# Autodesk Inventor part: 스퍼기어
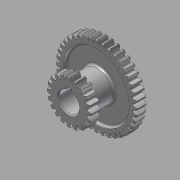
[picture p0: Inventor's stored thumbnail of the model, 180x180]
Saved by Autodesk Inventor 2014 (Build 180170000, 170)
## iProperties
Created: 2015-09
Part Number: 스퍼기어
Material: 강철, 연강
Document SubType Name: Modeling
Designer: mduedu
Density: 7.86 g/cm^3
Mass: 345.723 g
Surface Area: 225.641 cm^2
Volume: 43.9851 cm^3
Appearance: Steel
Author: mduedu
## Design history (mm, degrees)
sketch "스케치1"
  geometry: C1 r 38 at (0, 0); C2 r 40 at (0, 0); C3 r 35.5 at (0, 0); 1 further point
  constraints: 3 centre point, 3 coincident
  dimensions: "d0" = 76 diameter of C1; "d2" = 2 radial gap between concentric circles of C2 C1; "d3" = 71 diameter of C3 (computed from d0)
extrude "돌출1" new body sketch "스케치1" stored distance "d4" = 10; taper "d5" = 0 deg
sketch "스케치2"
  geometry: L1 (0, 35.5)-(0, -35.5); L2 (0, 0)-(40, 0); L3 (0, 0.57)-(39.996, 0.57); L4 (0, 1.57)-(39.969, 1.57); L5 (0, 2.07)-(39.946, 2.07); A1 r 35.5 centre (0, 0) between (0, 35.5) and (0, -35.5) reference; A2 r 40 centre (0, 0) between (40, 0) and (39.946, 2.07) reference; A3 r 9.234 centre (34.93, -7.149) between (39.996, 0.57) and (35.44, 2.07); A4 r 9.234 centre (34.93, 7.149) between (35.44, -2.07) and (39.996, -0.57); A5 r 40 centre (0, 0) between (39.996, -0.57) and (39.996, 0.57); A6 r 35.5 centre (0, 0) between (35.44, -2.07) and (35.44, 2.07); 4 further points
  constraints: 16 point on circle, 10 end point, 6 point on line, 4 centre point, 3 coincident, 3 parallel, 3 symmetric about line, 2 midpoint, 1 perpendicular, 1 vertical, 3 other
  dimensions: "d6" = 0.5 distance between parallel lines of L4 L5; "d8" = 1 distance between parallel lines of L3 L4; "d9" = 1.57 distance between parallel lines of L2 L4
extrude "돌출2" join sketch "스케치2" distance "d10" = 5; taper "d12" = 0 deg; dims "d11" = 5, "d13" = 0
fillet "모깎기1" dims "d17" = 0.5
chamfer "모따기1" distance "d21" = 1; stored, may be unused: second distance "d22" = 2, angle "d23" = 45 deg
sketch "스케치3"
  geometry: C1 r 32.5 at (0, 0); C2 r 15 at (0, 0); 1 further point
  constraints: 2 centre point, 2 coincident
  dimensions: "d27" = 65 diameter of C1; "d28" = 30 diameter of C2
extrude "돌출3" cut sketch "스케치3" distance "d29" = 3; taper "d30" = 0 deg
fillet "모깎기2" dims "d31" = 2
node "작업 평면2"
  node "작업 평면1"
sketch "스케치4"
  geometry: C1 r 15 at (0, 0) reference; 1 further point
extrude "돌출4" join sketch "스케치4" stored distance "d34" = 3; taper "d35" = 0 deg
sketch "스케치5"
  geometry: C1 r 17.5 at (0, 0); C2 r 20 at (0, 0); C3 r 22 at (0, 0); 1 further point
  constraints: 3 centre point, 3 coincident
  dimensions: "d36" = 40 diameter of C2; "d38" = 2 radial gap between concentric circles of C2 C3; "d39" = 35 diameter of C1 (= d36 - 2.5 x d38)
extrude "돌출6" join sketch "스케치5" distance "d46" = 10; taper "d47" = 0 deg
sketch "스케치6"
  geometry: L1 (0, 0)-(0, 22); L2 (-17.5, 0)-(17.5, 0); L3 (-0.57, 0)-(-0.57, 21.993); L4 (-1.57, 0)-(-1.57, 21.944); L5 (-2.07, 0)-(-2.07, 21.902); A1 r 22 centre (0, 0) between (0, 22) and (-0.57, 21.993) reference; A2 r 17.5 centre (0, 0) between (-17.5, 0) and (17.5, 0) reference; A3 r 9.431 centre (7.348, 16.868) between (-0.57, 21.993) and (-2.07, 17.377); A4 r 9.431 centre (-7.348, 16.868) between (2.07, 17.377) and (0.57, 21.993); A5 r 17.5 centre (0, 0) between (2.07, 17.377) and (-2.07, 17.377); A6 r 22 centre (0, 0) between (0.57, 21.993) and (-0.57, 21.993); 4 further points
  constraints: 16 point on circle, 10 end point, 5 point on line, 4 centre point, 3 coincident, 3 symmetric about line, 2 parallel, 2 perpendicular, 1 midpoint, 1 vertical, 3 other
  dimensions: "d40" = 0.5 distance between parallel lines of L4 L5; "d42" = 1 distance between parallel lines of L3 L4; "d43" = 1.57 distance between parallel lines of L1 L4
extrude "돌출5" join sketch "스케치6" distance "d44" = 10; taper "d45" = 0 deg
fillet "모깎기3" dims "d48" = 0.5
chamfer "모따기2" distance "d49" = 1; stored, may be unused: second distance "d50" = 2, angle "d51" = 45 deg
sketch "스케치7"
  geometry: C1 r 10 at (0, 0); 1 further point
  constraints: 1 centre point, 1 coincident
  dimensions: "d55" = 20 diameter of C1
extrude "돌출7" cut sketch "스케치7" stored distance "d56" = 10; taper "d57" = 0 deg
sketch "스케치8"
  geometry: L1 (-9.539, -3)-(-12.8, -3); L2 (-12.8, -3)-(-12.8, 3); L3 (-12.8, 3)-(-9.539, 3); L4 (-9.539, 3)-(-9.539, -3); A1 r 10 centre (0, 0) between (-9.539, -3) and (-9.539, 3) reference; 2 further points
  constraints: 8 end point, 3 point on circle, 2 parallel, 1 horizontal, 1 horizontal alignment, 1 perpendicular
  dimensions: "d58" = 6 distance of L1.end L2.end; "d60" = 22.8 distance from line of point (10, 0) L2
extrude "돌출8" cut sketch "스케치8" stored distance "d61" = 10; taper "d62" = 0 deg
chamfer "모따기3" distance "d63" = 1; stored, may be unused: second distance "d64" = 2, angle "d65" = 45 deg
fillet "모깎기4" dims "d66" = 2
node "솔리드1"
pattern_circular "원형 패턴3" dims "d25" = 360 deg
mirror "대칭1"
pattern_circular "원형 패턴4" dims "d53" = 360 deg
other parameters: "d32" = 5, "d33" = 42
